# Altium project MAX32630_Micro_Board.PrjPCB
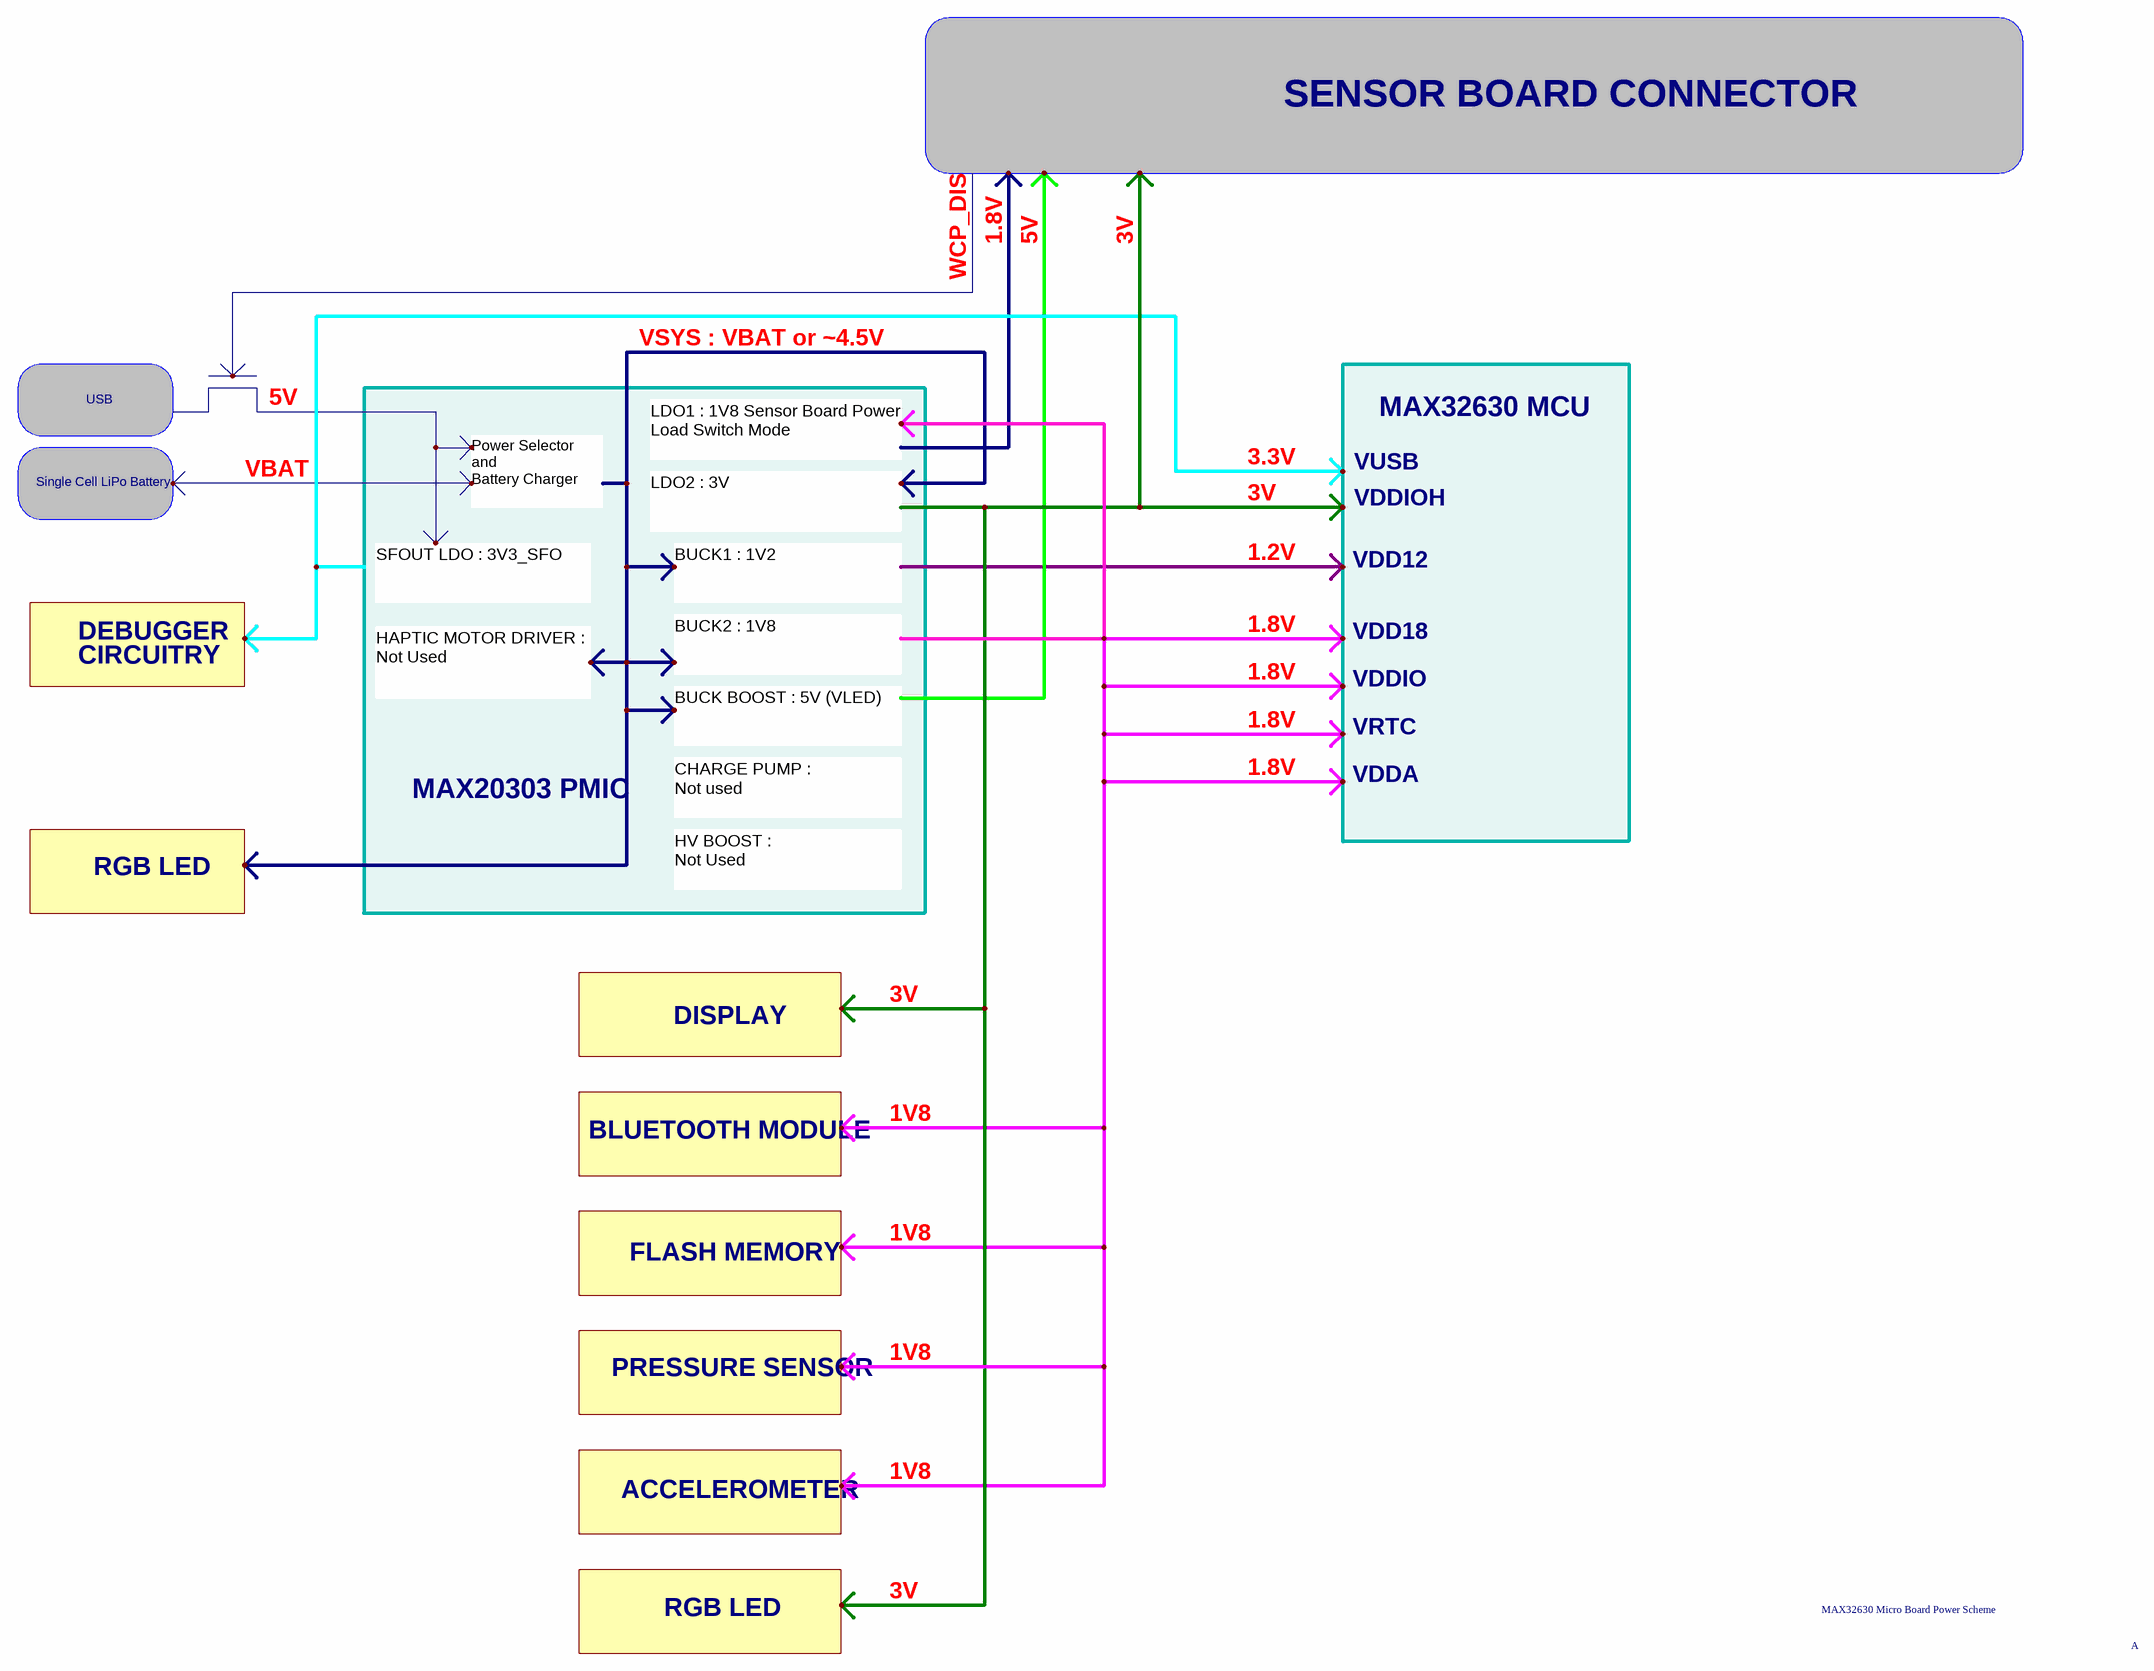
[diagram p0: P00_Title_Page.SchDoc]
2 sheets, 106 parts. Net scope: global (net labels, ports and power ports of the same name join across sheets).
Board file: MAX32630_Micro_Board.PcbDoc
Sheets:
  P00_Title_Page.SchDoc
  P01_MAX32630_Micro_Board.SchDoc

## Sheet P00_Title_Page.SchDoc
size C; SheetNumber: 1; PageSetup: Record=PageOptions¦CenterHorizontal=True¦CenterVertical=True¦PrintScale=0.54¦XCorrection=1.00¦YCorrection=1.00¦PrintKind=0¦BorderSize=5000000¦LeftOffset=0¦BottomOffset=0¦Orientation=2¦PaperLength=1000¦PaperWidth=1000¦Scale=100¦PaperSource=7¦PrintQuality=600¦MediaType=1¦DitherType=10¦PrintScaleMode=1¦PaperKind=A4¦PaperIndex=9

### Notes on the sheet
- SENSOR BOARD CONNECTOR
- 1.8V
- 5V
- 3V
- WCP_DIS
- VSYS : VBAT or ~4.5V
- USB
- MAX32630 MCU
- Single Cell LiPo Battery
- VBAT
- LDO1 : 1V8 Sensor Board Power
  Load Switch Mode
- 3.3V
- VUSB
- Power Selector and
  Battery Charger
- LDO2 : 3V
- VDDIOH
- SFOUT LDO : 3V3_SFO
- BUCK1 : 1V2
- 1.2V
- VDD12
- DEBUGGER
- CIRCUITRY
- BUCK2 : 1V8
- VDD18
- HAPTIC MOTOR DRIVER :
  Not Used
- VDDIO
- BUCK BOOST : 5V (VLED)
- VRTC
- VDDA
- MAX20303 PMIC
- CHARGE PUMP :
  Not used
- RGB LED
- HV BOOST :
  Not Used
- DISPLAY
- BLUETOOTH MODULE
- 1V8
- FLASH MEMORY
- PRESSURE SENSOR
- ACCELEROMETER
- MAX32630 Micro Board Power Scheme
- A

## Sheet P01_MAX32630_Micro_Board.SchDoc
size 508 x 381 mm; SheetNumber: 2; PageSetup: Record=PageOptions¦CenterHorizontal=True¦CenterVertical=True¦PrintScale=0.54¦XCorrection=1.00¦YCorrection=1.00¦PrintKind=0¦BorderSize=5000000¦LeftOffset=0¦BottomOffset=0¦Orientation=2¦PaperLength=1000¦PaperWidth=1000¦Scale=100¦PaperSource=7¦PrintQuality=600¦MediaType=1¦DitherType=10¦PrintScaleMode=1¦PaperKind=A4¦PaperIndex=9
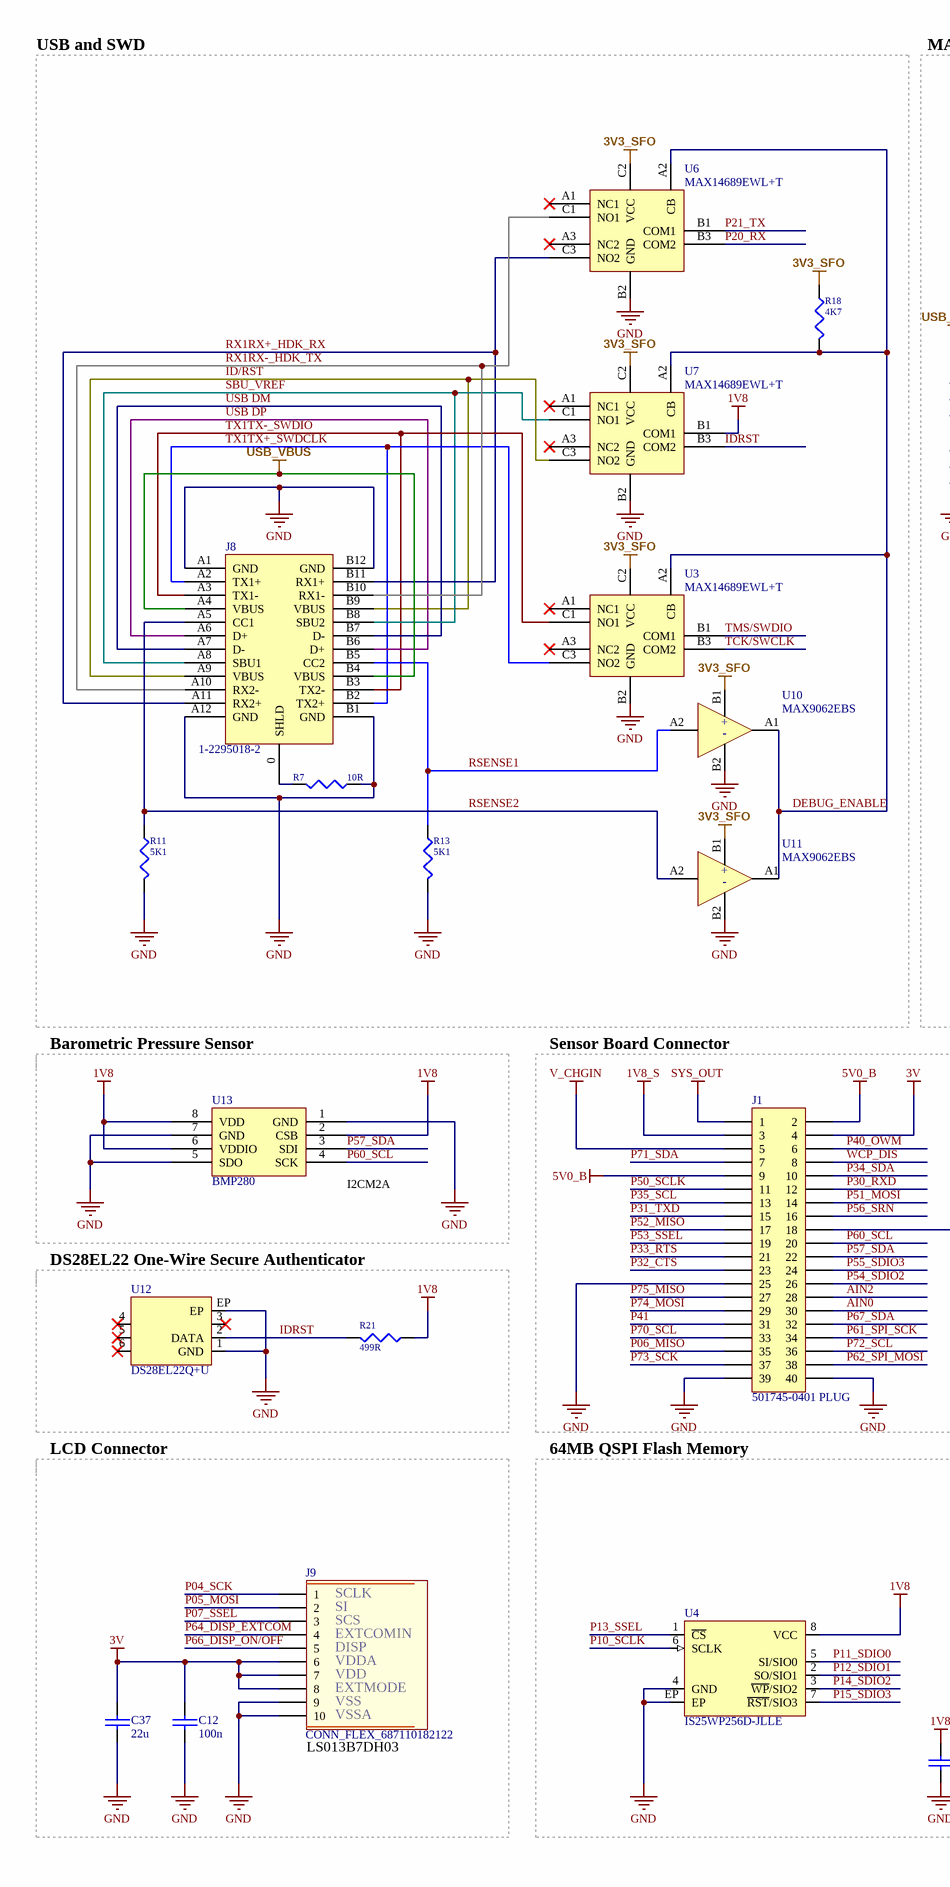
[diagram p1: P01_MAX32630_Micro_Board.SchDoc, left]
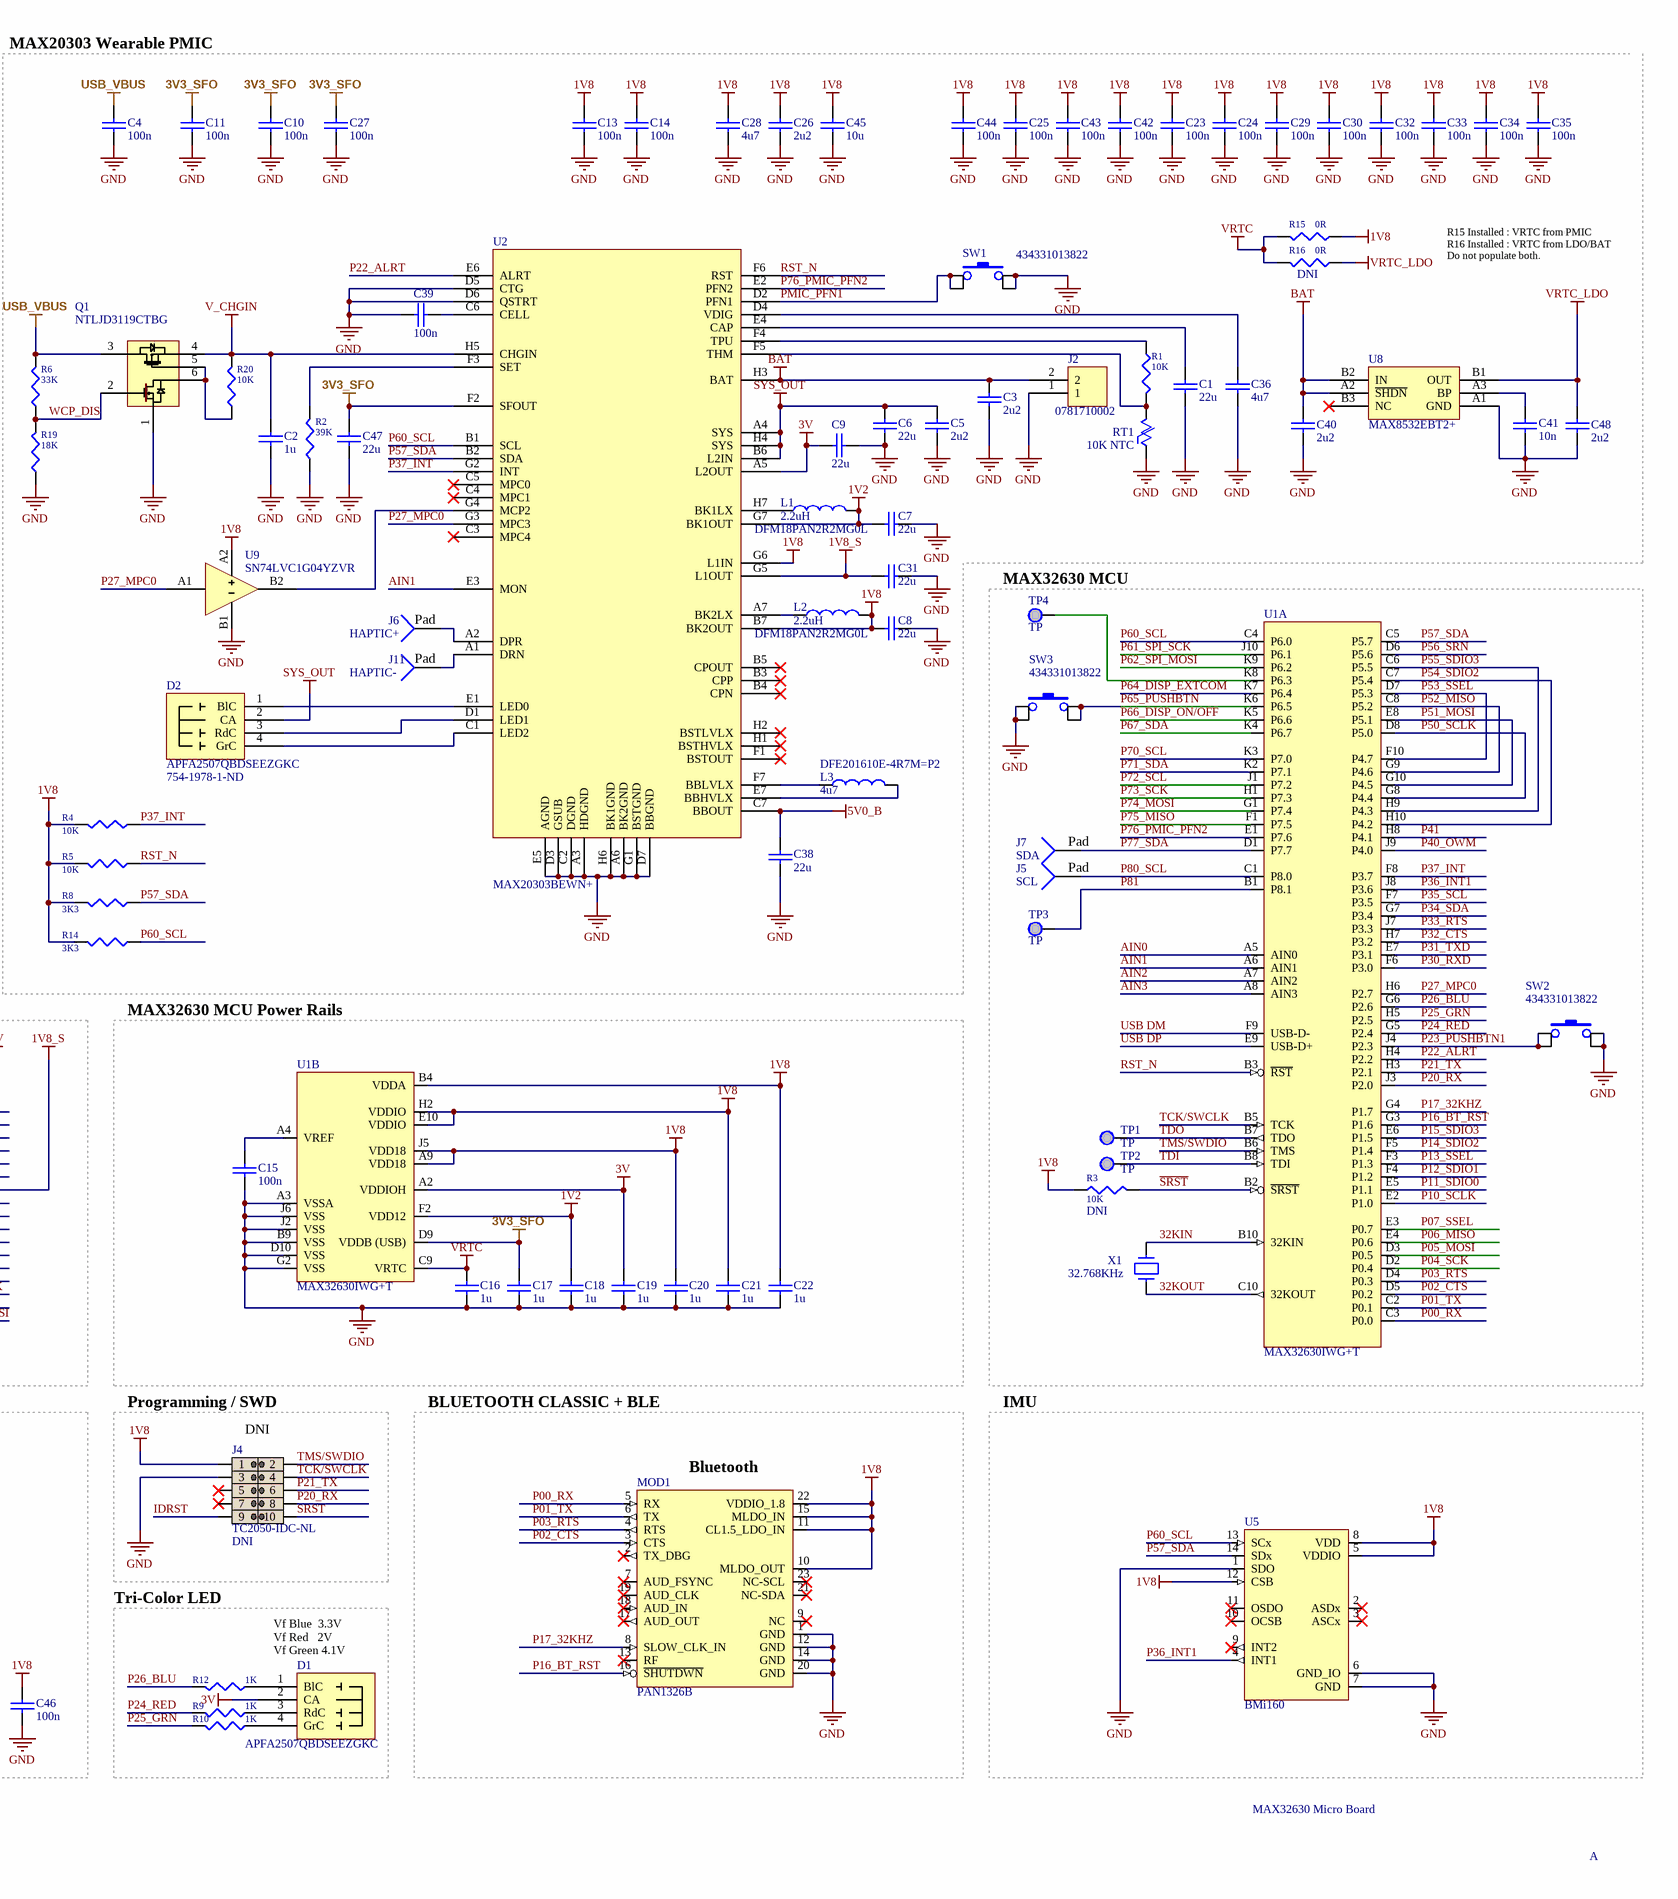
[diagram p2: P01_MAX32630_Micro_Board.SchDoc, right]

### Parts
C1  22u  [CAPACITOR_SMD_0603]
C2  1u  [CAPACITOR_SMD_0603]
C3  2u2  [CAPACITOR_SMD_0402]
C4  100n  [CAPACITOR_SMD_0201]
C5  2u2  [CAPACITOR_SMD_0402]
C6  22u  [CAPACITOR_SMD_0603]
C7  22u  [CAPACITOR_SMD_0603]
C8  22u  [CAPACITOR_SMD_0603]
C9  22u  [CAPACITOR_SMD_0603]
C10  100n  [CAPACITOR_SMD_0201]
C11  100n  [CAPACITOR_SMD_0201]
C12  100n  [CAPACITOR_SMD_0201]
C13  100n  [CAPACITOR_SMD_0402]
C14  100n  [CAPACITOR_SMD_0402]
C15  100n  [CAPACITOR_SMD_0201]
C16  1u  [CAPACITOR_SMD_0201]
C17  1u  [CAPACITOR_SMD_0201]
C18  1u  [CAPACITOR_SMD_0201]
C19  1u  [CAPACITOR_SMD_0201]
C20  1u  [CAPACITOR_SMD_0201]
C21  1u  [CAPACITOR_SMD_0201]
C22  1u  [CAPACITOR_SMD_0201]
C23  100n  [CAPACITOR_SMD_0201]
C24  100n  [CAPACITOR_SMD_0201]
C25  100n  [CAPACITOR_SMD_0201]
C26  2u2  [CAPACITOR_SMD_0402]
C27  100n  [CAPACITOR_SMD_0201]
C28  4u7  [CAPACITOR_SMD_0603]
C29  100n  [CAPACITOR_SMD_0201]
C30  100n  [CAPACITOR_SMD_0201]
C31  22u  [CAPACITOR_SMD_0603]
C32  100n  [CAPACITOR_SMD_0201]
C33  100n  [CAPACITOR_SMD_0201]
C34  100n  [CAPACITOR_SMD_0201]
C35  100n  [CAPACITOR_SMD_0201]
C36  4u7  [CAPACITOR_SMD_0603]
C37  22u  [CAPACITOR_SMD_0603]
C38  22u  [CAPACITOR_SMD_0603]
C39  100n  [CAPACITOR_SMD_0201]
C40  2u2  [CAPACITOR_SMD_0402]
C41  10n  [CAPACITOR_SMD_0201]
C42  100n  [CAPACITOR_SMD_0201]
C43  100n  [CAPACITOR_SMD_0201]
C44  100n  [CAPACITOR_SMD_0201]
C45  10u  [CAPACITOR_SMD_0603]
C46  100n  [CAPACITOR_SMD_0201]
C47  22u  [CAPACITOR_SMD_0603]
C48  2u2  [CAPACITOR_SMD_0402]
D1  APFA2507QBDSEEZGKC  [LED_APFA2507QBDSEEZGKC]
D2  APFA2507QBDSEEZGKC  Digikey Code: 754-1978-1-ND  [LED_APFA2507QBDSEEZGKC]
J1  501745-0401 PLUG  [501745-0401]
J2  0781710002  [CONN_MOLEX_781710002]
J4  TC2050-IDC-NL  Notes: DNI  [TC2050-IDC-NL]
J5  SCL  [SOLDERPAD_THD]
J6  HAPTIC+  [SOLDERPAD_THD]
J7  SDA  [SOLDERPAD_THD]
J8  1-2295018-2  [CONN_USB_1-2295018-2]
J9  CONN_FLEX_687110182122  [687110182122]
J11  HAPTIC-  [SOLDERPAD_THD]
L1  2.2uH  Manufacturer Part Number: DFM18PAN2R2MG0L  [0806INDUCTOR]
L2  2.2uH  Manufacturer Part Number: DFM18PAN2R2MG0L  [0806INDUCTOR]
L3  4u7  Manufacturer Part Number: DFE201610E-4R7M=P2  [INDUCTOR_0806]
MOD1  PAN1326B  [PAN1326B-BLUETOOTH]
Q1  NTLJD3119CTBG  [WDFN6]
R1  10K  [RESISTOR_SMD_0201]
R2  39K  [RESISTOR_SMD_0201]
R3  10K  Notes: DNI  [RESISTOR_SMD_0201]
R4  10K  [RESISTOR_SMD_0201]
R5  10K  [RESISTOR_SMD_0201]
R6  33K  [RESISTOR_SMD_0201]
R7  10R  [RESISTOR_SMD_0201]
R8  3K3  [RESISTOR_SMD_0201]
R9  1K  [RESISTOR_SMD_0201]
R10  1K  [RESISTOR_SMD_0201]
R11  5K1  [RESISTOR_SMD_0201]
R12  1K  [RESISTOR_SMD_0201]
R13  5K1  [RESISTOR_SMD_0201]
R14  3K3  [RESISTOR_SMD_0201]
R15  0R  [RESISTOR_SMD_0201]
R16  0R  Notes: DNI  [RESISTOR_SMD_0201]
R18  4K7  [RESISTOR_SMD_0201]
R19  18K  [RESISTOR_SMD_0201]
R20  10K  [RESISTOR_SMD_0201]
R21  499R  [RESISTOR_SMD_0201]
RT1  10K NTC  [RESISTOR_SMD_0201]
SW1  434331013822  [434331013822]
SW2  434331013822  [434331013822]
SW3  434331013822  [434331013822]
TP1  TP  [TP7]
TP2  TP  [TP7]
TP3  TP  [TP7]
TP4  TP  [TP7]
U1  MAX32630IWG+T  [WLP100 4X4MM 0.4MMP MOD1]  (parts A,B of 2)
U2  MAX20303BEWN+  [WLP56 0.5MMP]
U3  MAX14689EWL+T  [WLP9]
U4  IS25WP256D-JLLE  [WSON8_6x8]
U5  BMi160  [LGA14 3x2.5MM]
U6  MAX14689EWL+T  [WLP9]
U7  MAX14689EWL+T  [WLP9]
U8  MAX8532EBT2+  [UCSP6]
U9  SN74LVC1G04YZVR  [DSBGA4_S-XBGA-N4_YZV]
U10  MAX9062EBS  [UCSP4]
U11  MAX9062EBS  [UCSP4]
U12  DS28EL22Q+U  [TDFN6 3mm .95]
U13  BMP280  [BMP280]
X1  32.768KHz  [CRYSTAL-ABS07]

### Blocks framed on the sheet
USB and SWD: J8 R7 R11 R13 R18 U3 U6 U7 U10 U11
MAX32630 MCU: J5 J7 R3 SW2 SW3 TP1-TP4 U1 X1
Sensor Board Connector: J1
MAX32630 MCU Power Rails: C15-C22 U1
64MB QSPI Flash Memory: C46 U4
Programming / SWD: J4
IMU: U5
Tri-Color LED: D1 R9 R10 R12

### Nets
1V2: C7.2 C18.1 L1.2 U1.F2(VDD12) U2.G7(BK1OUT)
1V8: C8.2 C13.1 C14.1 C20.1 C21.1 C22.1 C23.1 C24.1 C25.1 C26.1 C28.1 C29.1 C30.1 C32.1 C33.1 C34.1 C35.1 C42.1 C43.1 C44.1 C45.1 C46.1 J4.1 L2.2 MOD1.10(MLDO_OUT) MOD1.11(CL1.5_LDO_IN) MOD1.15(MLDO_IN) MOD1.22(VDDIO_1.8) R3.1 R4.2 R5.2 R8.2 R14.2 R15.1 R21.1 U1.A9(VDD18) U1.B4(VDDA) U1.E10(VDDIO) U1.H2(VDDIO) U1.J5(VDD18) U2.B7(BK2OUT) U2.G6(L1IN) U4.8(VCC) U5.5(VDDIO) U5.8(VDD) U5.12(CSB) U7.B1(COM1) U9.A2(+) U13.2(CSB) U13.6(VDDIO) U13.8(VDD)
1V8_S: C31.1 J1.3 J1.18 U2.G5(L1OUT)
3V: C9.1 C12.2 C19.1 C37.1 D1.2(CA) J1.4 J9.6 J9.7 J9.8 U1.A2(VDDIOH) U2.A5(L2OUT)
3V3_SFO: C10.2 C11.2 C17.1 C27.1 C47.1 R18.1 U1.D9(VDDB_(USB)) U2.F2(SFOUT) U3.C2(VCC) U6.C2(VCC) U7.C2(VCC) U10.B1(VCC) U11.B1(VCC)
5V0_B: C38.1 J1.2 J1.9 U2.C7(BBOUT)
BAT: C3.1 C40.1 J2.2 U2.H3(BAT) U8.A2(~{SHDN}) U8.B2(IN)
GND: C1.2 C2.2 C3.2 C4.2 C5.2 C6.2 C7.1 C8.1 C9.2 C10.1 C11.1 C12.1 C13.2 C14.2 C15.2 C16.2 C17.2 C18.2 C19.2 C20.2 C21.2 C22.2 C23.2 C24.2 C25.2 C26.2 C27.2 C28.2 C29.2 C30.2 C31.2 C32.2 C33.2 C34.2 C35.2 C36.2 C37.2 C38.2 C39.1 C40.2 C41.2 C42.2 C43.2 C44.2 C45.2 C46.2 C47.2 C48.2 J1.25 J1.39 J1.40 J2.1 J4.3 J8.A1(GND) J8.A12(GND) J8.B1(GND) J8.B12(GND) J9.9 J9.10 MOD1.1(GND) MOD1.12(GND) MOD1.14(GND) MOD1.20(GND) Q1.1(S1) R2.1 R7.1 R11.2 R13.2 R19.1 RT1.1 SW1.3 SW1.4 SW2.3 SW2.4 SW3.3 SW3.4 U1.A3(VSSA) U1.B9(VSS) U1.D10(VSS) U1.G2(VSS) U1.J2(VSS) U1.J6(VSS) U2.A3(HDGND) U2.A6(BK2GND) U2.C2(DGND) U2.D3(GSUB) U2.D5(CTG) U2.D6(QSTRT) U2.D7(BBGND) U2.E5(AGND) U2.G1(BSTGND) U2.H6(BK1GND) U3.B2(GND) U4.4(GND) U4.EP U5.1(SDO) U5.6(GND_IO) U5.7(GND) U6.B2(GND) U7.B2(GND) U8.A1(GND) U9.B1(-) U10.B2(GND) U11.B2(GND) U12.1(GND) U12.EP U13.1(GND) U13.5(SDO) U13.7(GND)
SYS_OUT: C5.1 C6.1 D2.2(CA) J1.1 U2.A4(SYS) U2.B6(L2IN) U2.H4(SYS)
USB_VBUS: C4.1 J8.A4(VBUS) J8.B4(VBUS) Q1.3(D2) R6.2
V_CHGIN: C2.1 J1.5 Q1.4(S2) R20.2 U2.H5(CHGIN)
VRTC: C16.1 R15.2 R16.2 U1.C9(VRTC)
VRTC_LDO: C48.1 R16.1 U8.B1(OUT)
32KIN: U1.B10(32KIN) X1.2
32KOUT: U1.C10(32KOUT) X1.1
AIN0: J1.30 U1.A5(AIN0)
AIN1: U1.A6(AIN1) U2.E3(MON)
AIN2: J1.28 U1.A7(AIN2)
AIN3: U1.A8(AIN3)
DEBUG_ENABLE: R18.2 U3.A2(CB) U6.A2(CB) U7.A2(CB) U10.A1(OUT) U11.A1(OUT)
ID/~{RST}: J8.A9(VBUS) J8.B9(VBUS) U7.C3(NO2)
IDRST: J4.9 R21.2 U7.B3(COM2) U12.2(DATA)
P00_RX: MOD1.5(RX) U1.C3(P0.0)
P01_TX: MOD1.6(TX) U1.C2(P0.1)
P02_CTS: MOD1.3(CTS) U1.D5(P0.2)
P03_RTS: MOD1.4(RTS) U1.D4(P0.3)
P04_SCK: J9.1 U1.D2(P0.4)
P05_MOSI: J9.2 U1.D3(P0.5)
P06_MISO: J1.35 U1.E4(P0.6)
P07_SSEL: J9.3 U1.E3(P0.7)
P10_SCLK: U1.E2(P1.0) U4.6(SCLK)
P11_SDIO0: U1.E5(P1.1) U4.5(SI/SIO0)
P12_SDIO1: U1.F4(P1.2) U4.2(SO/SIO1)
P13_SSEL: U1.F3(P1.3) U4.1(~{CS})
P14_SDIO2: U1.F5(P1.4) U4.3(~{WP}/SIO2)
P15_SDIO3: U1.E6(P1.5) U4.7(~{RST}/SIO3)
P16_BT_RST: MOD1.16(~{SHUTDWN}) U1.G3(P1.6)
P17_32KHZ: MOD1.8(SLOW_CLK_IN) U1.G4(P1.7)
P20_RX: J4.8 U1.J3(P2.0) U6.B3(COM2)
P21_TX: J4.6 U1.H3(P2.1) U6.B1(COM1)
P22_ALRT: U1.H4(P2.2) U2.E6(ALRT)
P23_PUSHBTN1: SW2.1 SW2.2 U1.J4(P2.3)
P24_RED: R9.2 U1.G5(P2.4)
P25_GRN: R10.2 U1.H5(P2.5)
P26_BLU: R12.2 U1.G6(P2.6)
P27_MPC0: U1.H6(P2.7) U2.G3(MPC3) U9.A1(A)
P30_RXD: J1.12 U1.F6(P3.0)
P31_TXD: J1.15 U1.E7(P3.1)
P32_CTS: J1.23 U1.H7(P3.2)
P33_RTS: J1.21 U1.J7(P3.3)
P34_SDA: J1.10 U1.G7(P3.4)
P35_SCL: J1.13 U1.F7(P3.5)
P36_INT1: U1.J8(P3.6) U5.4(INT1)
P37_INT: R4.1 U1.F8(P3.7) U2.G2(INT)
P40_OWM: J1.6 U1.J9(P4.0)
P41: J1.31 U1.H8(P4.1)
P50_SCLK: J1.11 U1.D8(P5.0) U1.G8(P4.4)
P51_MOSI: J1.14 U1.E8(P5.1) U1.G10(P4.5)
P52_MISO: J1.17 U1.C8(P5.2) U1.G9(P4.6)
P53_SSEL: J1.19 U1.D7(P5.3) U1.F10(P4.7)
P54_SDIO2: J1.26 U1.C7(P5.4) U1.H10(P4.2)
P55_SDIO3: J1.24 U1.C6(P5.5) U1.H9(P4.3)
P56_SRN: J1.16 U1.D6(P5.6)
P57_SDA: J1.22 R8.1 U1.C5(P5.7) U2.B2(SDA) U5.14(SDx) U13.3(SDI)
P60_SCL: J1.20 R14.1 U1.C4(P6.0) U2.B1(SCL) U5.13(SCx) U13.4(SCK)
P61_SPI_SCK: J1.34 U1.J10(P6.1)
P62_SPI_MOSI: J1.38 U1.K9(P6.2)
P64_DISP_EXTCOM: J9.4 U1.K7(P6.4)
P65_PUSHBTN: SW3.1 SW3.2 U1.K6(P6.5)
P66_DISP_ON/~{OFF}: J9.5 U1.K5(P6.6)
P67_SDA: J1.32 U1.K4(P6.7)
P70_SCL: J1.33 U1.K3(P7.0)
P71_SDA: J1.7 U1.K2(P7.1)
P72_SCL: J1.36 U1.J1(P7.2)
P73_SCK: J1.37 U1.H1(P7.3)
P74_MOSI: J1.29 U1.G1(P7.4)
P75_MISO: J1.27 U1.F1(P7.5)
P76_PMIC_PFN2: U1.E1(P7.6) U2.E2(PFN2)
P77_SDA: J7.1 U1.D1(P7.7)
P80_SCL: J5.1 U1.C1(P8.0)
P81: TP3.1 U1.B1(P8.1)
PMIC_PFN1: SW1.1 SW1.2 U2.D2(PFN1)
RSENSE1: J8.B5(CC2) R13.1 U10.A2(IN)
RSENSE2: J8.A5(CC1) R11.1 U11.A2(IN)
RST_N: R5.1 U1.B3(~{RST}) U2.F6(RST)
RX1RX+_HDK_RX: J8.A11(RX2+) J8.B11(RX1+) U6.C3(NO2)
RX1RX-_HDK_TX: J8.A10(RX2-) J8.B10(RX1-) U6.C1(NO1)
~{SRST}: J4.10 R3.2 U1.B2(~{SRST})
SBU_VREF: J8.A8(SBU1) J8.B8(SBU2) U7.C1(NO1)
TCK/SWCLK: J4.4 U1.B5(TCK) U3.B3(COM2)
TDI: TP2.1 U1.B8(TDI)
TDO: TP1.1 U1.B7(TDO)
TMS/SWDIO: J4.2 U1.B6(TMS) U3.B1(COM1)
TX1TX+_SWDCLK: J8.A2(TX1+) J8.B2(TX2+) U3.C3(NO2)
TX1TX-_SWDIO: J8.A3(TX1-) J8.B3(TX2-) U3.C1(NO1)
USB DM: J8.A7(D-) J8.B7(D-) U1.F9(USB-D-)
USB DP: J8.A6(D+) J8.B6(D+) U1.E9(USB-D+)
WCP_DIS: J1.8 Q1.2(G1) R6.1 R19.2
NetC1_1: C1.1 U2.E4(CAP)
NetC15_1: C15.1 U1.A4(VREF)
NetC36_1: C36.1 U2.D4(VDIG)
NetC39_2: C39.2 U2.C6(CELL)
NetC41_1: C41.1 U8.A3(BP)
NetD1_1: D1.1(BlC) R12.1
NetD1_3: D1.3(RdC) R9.1
NetD1_4: D1.4(GrC) R10.1
NetD2_1: D2.1(BlC) U2.E1(LED0)
NetD2_3: D2.3(RdC) U2.D1(LED1)
NetD2_4: D2.4(GrC) U2.C1(LED2)
NetJ6_1: J6.1 U2.A2(DPR)
NetJ8_0: J8.0(SHLD) R7.2
NetJ11_1: J11.1 U2.A1(DRN)
NetL1_1: L1.1 U2.H7(BK1LX)
NetL2_1: L2.1 U2.A7(BK2LX)
NetL3_1: L3.1 U2.F7(BBLVLX)
NetL3_2: L3.2 U2.E7(BBHVLX)
NetQ1_5: Q1.5(G2) Q1.6(D1) R20.1
NetR1_1: R1.1 U2.F4(TPU)
NetR1_2: R1.2 RT1.2 U2.F5(THM)
NetR2_2: R2.2 U2.F3(SET)
NetTP4_1: TP4.1 U1.K8(P6.3)
NetU2_G4: U2.G4(MCP2) U9.B2(Y)

Not connected (* = marked no-connect by the designer): J4 5* 7*; MOD1 2(TX_DBG)* 7(AUD_FSYNC)* 9(NC)* 13(RF)* 17(AUD_OUT)* 18(AUD_IN)* 19(AUD_CLK)* 21(NC-SDA)* 23(NC-SCL)*; U2 B3(CPP)* B4(CPN)* B5(CPOUT)* C3(MPC4)* C4(MPC1)* C5(MPC0)* F1(BSTOUT)* H1(BSTHVLX)* H2(BSTLVLX)*; U3 A1(NC1)* A3(NC2)*; U5 2(ASDx)* 3(ASCx)* 9(INT2)* 10(OCSB)* 11(OSDO)*; U6 A1(NC1)* A3(NC2)*; U7 A1(NC1)* A3(NC2)*; U8 B3(NC)*; U12 3* 4* 5* 6*

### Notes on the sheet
- MAX20303 Wearable PMIC
- R15 Installed : VRTC from PMIC
  R16 Installed : VRTC from LDO/BAT
  Do not populate both.
- (near J6) Pad
- (near J11) Pad
- (near J7) Pad
- Pad
- Barometric Pressure Sensor
- (near U13) I2CM2A
- (near U12) DS28EL22 One-Wire Secure Authenticator
- LCD Connector
- (near J4) DNI
- BLUETOOTH CLASSIC + BLE
- (near MOD1) Bluetooth
- (near J9) SI
- (near J9) SCLK
- (near J9) VDD
- (near J9) VDDA
- (near J9) DISP
- (near J9) EXTCOMIN
- (near J9) SCS
- (near J9) LS013B7DH03
- (near J9) VSSA
- (near J9) VSS
- (near J9) EXTMODE
- Vf Blue  3.3V
  Vf Red   2V
  Vf Green 4.1V
- MAX32630 Micro Board
- A

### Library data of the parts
C1 C6-C9 C31 C37 C38 C47 = CAP_0603_22u: CAP CER 22UF 6.3V X5R 0603; Manufacturer Part Number: GRM188R60J226MEA0D; Manufacturer: Murata Electronics North America
C2 = CAP_0603_1u: CAP CER 1UF 16V X5R 0603; Manufacturer Part Number: GRM188R61C105KA12D; Manufacturer: Murata Electronics North America
C3 C5 C26 = CAP_0402_2u2: CAP CER 2.2UF 10V X5R 0402; Manufacturer Part Number: GRM155R61A225KE95D; Manufacturer: Murata Electronics North America
C4 C10-C12 C15 C23-C25 C27 C29 C30 C32-C35 C39 C42-C44 C46 = CAP_0201_100n: CAP CER 0.1UF 10V X5R 0201; Manufacturer Part Number: GRM033R61A104KE15D; Manufacturer: Murata Electronics North America
C13 C14 = CAP_0402_100n: CAP CER 0.1UF 16V X7R 0402; Manufacturer Part Number: GRM155R71C104KA88D; Manufacturer: Murata Electronics North America
C16-C22 = CAP_0201_1u: CAP CER 1UF 10V X6S 0201; Manufacturer Part Number: GRM033C81A105ME05D; Manufacturer: Murata Electronics North America
C28 C36 = CAP_0603_4u7: CAP CER 4.7UF 10V X5R 0603; Manufacturer Part Number: GRM188R61A475KE15D; Manufacturer: Murata Electronics North America
C40 C48 = CAP_0402_2u2: CAP CER 2.2UF 10V X5R 0402; Manufacturer: Murata Electronics North America; Manufacturer Part Number: GRM155R61A225KE95D
C41 = CAP_0201_10n: CAP CER 10000PF 10V X7R 0201; Manufacturer: Murata Electronics North America; Manufacturer Part Number: GRM033R71A103KA01D
C45 = CAP_0603_10u: CAP CER 10UF 16V X5R 0603; Manufacturer Part Number: GRM188R61C106KAALD; Manufacturer: Murata Electronics North America
D1 D2 = LED_APFA2507QBDSEEZGKC: 2.5 x 0.7 mm Right Angle SMD Chip LED Lamp; Manufacturer: Kingbright
J1 = CONN_MOLEX_5017450401: CONN PLUG 40POS 0.4MM SMD GOLD; Manufacturer: Molex
J2 = CONN_MOLEX_0781710002: 1.20MM WTB HEADER VERT 2POS; Manufacturer: Molex
J4 = JUMPBLOCK 5: CONN HEADER 10POS DUAL .05" SMD; Manufacturer Part Number: 20021521-00010T1LF; Manufacturer: Amphenol FCI
J5-J7 J11 = SolderPad_TH: PCB Pad; Manufacturer Part Number: Not a component; Notes: DNI
J8 = CONN_USB_1-2295018-2: TE Connectivity USB TYPE C, REC OFFSET 0.65MM DU; Manufacturer: TE Connectivity AMP Connectors
J9 = CONN_FLEX_687110182122: 0.50 mm SMT ZIF Horizontal Dual Contact WR-FPC, 10 pins; Manufacturer: Wurth Elektronik
L1 L2 = INDUCTOR1: INDUCTOR 2.2UH 1.5A 160 mOHM; Manufacturer: Murata
L3 = INDUCTOR1: INDUCTOR 4.7UH 1.5A 160 mOHM; Manufacturer: Murata
MOD1 = PAN1326B: BLUETOOTH PAN1326B CC2564B HCI A; Manufacturer: Panasonic Electronic Components; Manufacturer Part Number: ENW-89823A3KF
Q1 = NTLJD3119CTBG: 20 V/−20 V, 4.6 A/−4.1 A, Complementary Power MOSFET; Manufacturer: On Semiconductor
R1 R3-R5 R20 = RES_0201_10K: RES SMD 10K OHM 1% 1/20W 0201; Manufacturer: Panasonic Electronic Components; Manufacturer Part Number: ERJ-1GEF1002C
R2 = RES_0201_39K: RES SMD 39K OHM 1% 1/20W 0201; Manufacturer: Panasonic Electronic Components; Manufacturer Part Number: ERJ-1GEF3902C
R6 = RES_0201_33K: RES SMD 33K OHM 1% 1/20W 0201; Manufacturer: Panasonic Electronic Components; Manufacturer Part Number: ERJ-1GEF3302C
R7 = RES_0201_10R: RES SMD 10 OHM 1% 1/20W 0201; Manufacturer: Panasonic Electronic Components; Manufacturer Part Number: ERJ-1GEF10R0C
R8 R14 = RES_0201_3K3: RES SMD 3K3 OHM 5% 1/20W 0201; Manufacturer: Panasonic Electronic Components; Manufacturer Part Number: ERJ-1GEJ332C
R9 R10 R12 = RES_0201_1K: RES SMD 1K OHM 1% 1/20W 0201; Manufacturer: Panasonic Electronic Components; Manufacturer Part Number: ERJ-1GEF1001C
R11 R13 = RES_0201_5K1: RES SMD 5K1 OHM 1% 1/20W 0201; Manufacturer: Panasonic Electronic Components; Manufacturer Part Number: ERJ-1GEJ512C
R15 R16 = RES_0201_0R: RES SMD 0 OHM JUMPER 1/20W 0201; Manufacturer: Panasonic Electronic Components; Manufacturer Part Number: ERJ-1GN0R00C
R18 = RES_0201_4K7: RES SMD 4.7K OHM 1% 1/20W 0201; Manufacturer: Panasonic Electronic Components; Manufacturer Part Number: ERJ-1GEF4701C
R19 = RES_0201_18K: RES SMD 18K OHM 1% 1/20W 0201; Manufacturer: Panasonic Electronic Components; Manufacturer Part Number: ERJ-1GEF1802C
R21 = RES_0201_499R: RES SMD 499R 5% 1/20W 0201; Manufacturer: Panasonic Electronic Components; Manufacturer Part Number: ERJ-1GEF4990C
RT1 = THERMISTOR_0201_10K: NTC THERMISTOR 10K OHM 1% 0201; Manufacturer Part Number: NCP03XH103F05RL; Manufacturer: Murata
SW1-SW3 = SW-PB-434331013822: SWITCH TACTILE SPST-NO 0.02A 15V; Manufacturer: Wurth
TP1-TP4 = TP: Test Point; Manufacturer: Not a component; Notes: DNI
U1 = MAX32630IWG+T: Ultra-Low Power Cortex-M4F Microcontroller for Rechargeable Devices; Manufacturer: Maxim Integrated
U2 = MAX20303BEWN+: Wearable PMIC; Manufacturer: Maxim Integrated
U3 U6 U7 = MAX14689EWL+T: Ultra-Small, Low-RON, Beyond-the-Rails DPDT Analog Switches; Manufacturer: Maxim Integrated
U4 = IS25WP256D-JLLE: IC FLASH 256M SPI 104MHZ 8WSON; Manufacturer: ISSI, Integrated Silicon Solution Inc
U5 = BMi160: Inertial Measurement Unit, Low Power 14pin; Manufacturer: Bosch Sensortec
U8 = MAX8532EBT2+: IC REG LINEAR 200MA 6-UCSP; Manufacturer: Maxim Integrated
U9 = SN74LVC1G04YZVR: SN74LVC1G04 Single Inverter Gate; Manufacturer: Texas Instruments
U10 U11 = MAX9062EBS+T: Ultra-Small, nanoPower Single Comparators in 4-Bump UCSP; Manufacturer: Maxim Integrated
U12 = DS28EL22Q+U: 1-WIRE SHA-256 SECURE AUTHENTICATOR WITH 2KBIT EEPROM; Manufacturer: Maxim Integrated
U13 = BMP280: Digital Pressure Sensor; Manufacturer: Bosch Sensortec
X1 = CRYSTAL_ABS07-32.768KHZ-6-T: CRYSTAL 32.768KHZ 6.0PF SMD; Manufacturer: Abracon Corporation

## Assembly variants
MAX32630HSP3_REV_A: not fitted J4 J5 J6 J7 J11 R3 R16 TP1 TP2 TP3 TP4 U8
